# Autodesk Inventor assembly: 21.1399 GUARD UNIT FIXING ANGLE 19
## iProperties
Created: 2007-01
Part Number: 21.1399 GUARD UNIT FIXING ANGLE 19
Document SubType Name: Assembly
Designer: Andy Moles
Author: Andy Moles
